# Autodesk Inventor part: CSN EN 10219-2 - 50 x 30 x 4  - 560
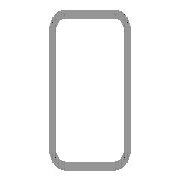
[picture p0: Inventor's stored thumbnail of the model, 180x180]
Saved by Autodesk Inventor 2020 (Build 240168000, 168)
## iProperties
Created: 2019-01
Part Number: CSN EN 10219-2 - 50 x 30 x 4  - 560
Material: Ocel, měkká
Description: Duté svařované profily tvářené za studena z nelegované a jemnozrnné konstrukční oceli
Document SubType Name: Modeling
Standard: CSN EN 10219-2
Designer: doma
Standards Organization: CSN
Language: cs-CZ
Size Designation: 50 x 30 x 4  - 560
Categories: <MemberInstance><Categories><Category DisplayName="Konstrukční profily" InternalName="089c4875-fa83-4c05-b084-43b9cc11f5ed" Mnemonic="GRDR"><CategoryParameter D
Stock Number: 50 x 30 x 4
Density: 7.85 g/cm^3
Appearance: Pololeštěná
Mass: 2289.31 g
Surface Area: 1481.42 cm^2
Volume: 291.632 cm^3
IsCustomPart: 1
G_L: 560,000 mm
Author: doma
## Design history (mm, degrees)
node "Počáteční rovina"
node "Koncová rovina"
sketch "Náčrt"
  geometry: L1 (-15, -17)-(-15, 17); L2 (-7, 25)-(7, 25); L3 (15, 17)-(15, -17); L4 (7, -25)-(-7, -25); L5 (-7, 21)-(7, 21); L6 (11, 17)-(11, -17); L7 (7, -21)-(-7, -21); L8 (-11, -17)-(-11, 17); L9 (0, 37.32)-(0, -37.32) reference; L10 (-23.32, 0)-(23.32, 0) reference; A1 r 8 centre (-7, -17) between (-15, -17) and (-7, -25); A2 r 8 centre (-7, 17) between (-7, 25) and (-15, 17); A3 r 8 centre (7, 17) between (15, 17) and (7, 25); A4 r 8 centre (7, -17) between (7, -25) and (15, -17); A5 r 4 centre (-7, 17) between (-7, 21) and (-11, 17); A6 r 4 centre (7, 17) between (11, 17) and (7, 21); A7 r 4 centre (7, -17) between (7, -21) and (11, -17); A8 r 4 centre (-7, -17) between (-11, -17) and (-7, -21)
  constraints: 16 end point, 16 point on circle, 8 centre point, 8 tangent, 4 parallel, 3 equal radius, 2 perpendicular, 7 other
  dimensions: "d7" = 8 radius of A1 (= G_IR); "d10" = 50 distance between parallel lines of L2 L4 (= G_H); "d11" = 30 distance between parallel lines of L1 L3 (= G_W); "d12" = 4 distance between parallel lines of L3 L6 (= G_T); "d15" = 25 distance between parallel lines of L2 L10 (= 0.5 x d10); "d16" = 15 distance between parallel lines of L9 L3 (= 0.5 x d11)
extrude "Těleso" new body sketch "Náčrt" stored distance "d3" = 520; taper "d4" = 0 deg
node "Driven Length"
  sketch "Sketch3"
    geometry: L1 (0, 0)-(10, 0) reference
    constraints: 2 end point, 1 horizontal
  workplane "Work Plane3"
  sketch "Sketch4"
    geometry: L1 (-2, 0)-(12, 0) reference; L2 (-2, 560)-(12, 560) reference
    dimensions: "d18" = 560 distance between parallel lines of L1 L2 (derived)
sketch "Náčrt5"
  geometry: L1 (40, 17)-(245, 17); L2 (355, 17)-(560, 17); L3 (40, 0)-(40, 34) reference
  constraints: 4 end point, 2 collinear, 1 horizontal, 1 midpoint
  dimensions: "d19" = 110 distance of L1.end L2.start
hole "Díra1" sketch "Náčrt5" at (245, 17), (355, 17) diameter "d20" = 25; stored, may be unused: countersink angle "d24" = 90 deg, drill point angle "d26" = 118 deg; dims "d21" = 6, "d22" = 4, "d23" = 2, "d25" = 8
chamfer "Zkosení1" distance "d27" = 2; stored, may be unused: second distance "d28" = 2, angle "d29" = 45 deg
body "Solid1"
other parameters: "G_W" = 30 [user parameter; used in 1 equation term], "G_H" = 50 [user parameter; used in 1 equation term], "G_T" = 4 [user parameter; used in 1 equation term], "G_IR" = 8 [user parameter; used in 1 equation term], "G_L" = 560 (= d18) [user parameter], "G_OFFSET_START" = 0 [user parameter; used in 1 equation term], "G_OFFSET_END" = 0 [user parameter; used in 1 equation term], "d13" = 0 (computed from G_OFFSET_START), "d17" = 90 deg
